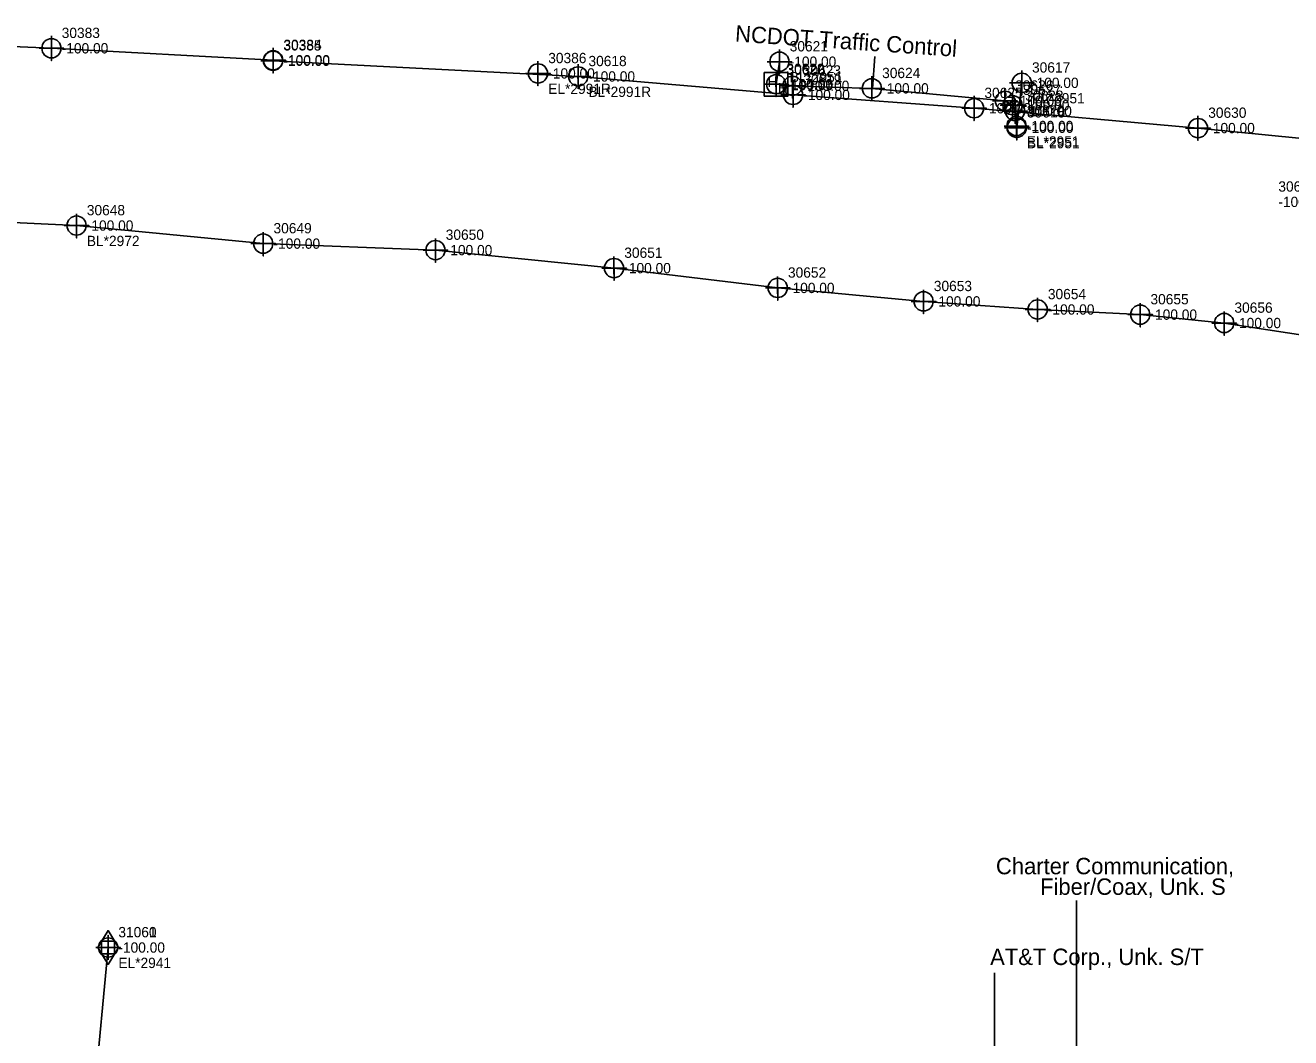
# Model space of a CAD drawing. Extents: x 2083698 to 2094313, y 743246 to 752873.
# Drawn here: x 2089753.4 to 2090061.4, y 744411.5 to 744658 of the extents above; entities that cross this region are included whole.
import ezdxf

# ---------------------------------------------------------------- set-up
doc = ezdxf.new("R2010")
doc.units = 0
for name, color, linetype in [('COGO Default Chain', 7, 'Continuous'), ('COGO Default Curve', 7, 'Continuous'), ('COGO Default Point Number', 7, 'Continuous'), ('COGO Default Spiral', 7, 'Continuous'), ('Exist Other Culture Fence Line', 7, 'Continuous'), ('Exist Property Iron Pin Leader', 7, 'Continuous'), ('Exist Property Iron Pin Text', 7, 'Continuous'), ('Exist Property Line', 7, 'Continuous'), ('Exist Property Monument Cogo Elevation', 7, 'Continuous'), ('Exist Property Monument Cogo Number', 7, 'Continuous'), ('Exist Property Monument Leader', 7, 'Continuous'), ('Exist Property Monument Text', 7, 'Continuous'), ('Exist Right of Way Easement Line', 7, 'Continuous'), ('Exist Right of Way Line', 7, 'Continuous'), ('Exist Right of Way Line Leader', 7, 'Continuous'), ('Exist Right of Way Line Text', 7, 'Continuous'), ('Exist Right of Way Width CELL', 7, 'Continuous'), ('Exist Utilities Gas Meter CELL', 7, 'Continuous'), ('Exist Utilities Gas Meter Cogo Elevation', 7, 'Continuous'), ('Exist Utilities Gas Meter Cogo Number', 7, 'Continuous'), ('Exist Utilities Gas UG Line SUE LOS B', 7, 'Continuous'), ('Exist Utilities Power UG Cable SUE LOS B', 7, 'Continuous'), ('Exist Utilities Power UG Cable SUE LOS B Leader', 7, 'Continuous'), ('Exist Utilities Power UG Cable SUE LOS B Text', 7, 'Continuous'), ('Exist Utilities Telephone UG Conduit SUE LOS B', 7, 'Continuous'), ('Exist Utilities Telephone UG Conduit SUE LOS B Leader', 7, 'Continuous'), ('Exist Utilities Telephone UG Conduit SUE LOS B Text', 7, 'Continuous'), ('Exist Utilities TV UG Cable SUE LOS B Leader', 7, 'Continuous'), ('Exist Utilities TV UG Cable SUE LOS B Text', 7, 'Continuous'), ('Exist Utilities Water UG Line SUE LOS B', 7, 'Continuous'), ('Old_Level_20', 7, 'Continuous'), ('Scratch_Level_2', 7, 'Continuous'), ('Scratch_Level_3', 7, 'Continuous'), ('Scratch_Level_5', 7, 'Continuous')]:
    doc.layers.add(name, color=color, linetype=linetype)

msp = doc.modelspace()

# ---------------------------------------------------------------- linework, layer by layer
at = {"layer": 'COGO Default Curve'}
msp.add_lwpolyline([(2089770.58, 744433.44), (2089776.58, 744433.44), (2089773.58, 744433.44), (2089773.58, 744436.44), (2089773.58, 744430.44)], dxfattribs=at)
msp.add_circle((2089773.58, 744433.44), 2.34, dxfattribs=at)
at = {"layer": 'COGO Default Point Number'}
for points in [[(2089759.79, 744655.4), (2089759.79, 744649.4), (2089759.79, 744652.4), (2089762.79, 744652.4), (2089756.79, 744652.4)], [(2089813.73, 744652.36), (2089813.73, 744646.36), (2089813.73, 744649.36), (2089816.73, 744649.36), (2089810.73, 744649.36)], [(2089813.76, 744652.5), (2089813.76, 744646.5), (2089813.76, 744649.5), (2089816.76, 744649.5), (2089810.76, 744649.5)], [(2089878.21, 744649.28), (2089878.21, 744643.28), (2089878.21, 744646.28), (2089881.21, 744646.28), (2089875.21, 744646.28)], [(2089888, 744648.55), (2089888, 744642.55), (2089888, 744645.55), (2089891, 744645.55), (2089885, 744645.55)], [(2089940.29, 744644.05), (2089940.29, 744638.05), (2089940.29, 744641.05), (2089943.29, 744641.05), (2089937.29, 744641.05)], [(2089984.37, 744640.8), (2089984.37, 744634.8), (2089984.37, 744637.8), (2089987.37, 744637.8), (2089981.37, 744637.8)], [(2090038.85, 744635.97), (2090038.85, 744629.97), (2090038.85, 744632.97), (2090041.85, 744632.97), (2090035.85, 744632.97)]]:
    msp.add_lwpolyline(points, dxfattribs=at)
for centre in [(2089759.79, 744652.4), (2089813.73, 744649.36), (2089813.76, 744649.5), (2089878.21, 744646.28), (2089888, 744645.55), (2089940.29, 744641.05), (2089984.37, 744637.8), (2090038.85, 744632.97)]:
    msp.add_circle(centre, 2.34, dxfattribs=at)
at = {"layer": 'COGO Default Spiral'}
msp.add_line((2089936.22, 744643.45), (2089936.22, 744643.45), dxfattribs=at)
msp.add_lwpolyline([(2089933.27, 744640.72), (2089939.02, 744640.72), (2089939.02, 744646.47), (2089933.27, 744646.47), (2089933.27, 744640.72)], dxfattribs=at)
at = {"layer": 'Exist Property Iron Pin Text'}
for points in [[(2089936.98, 744652.14), (2089936.98, 744646.14), (2089936.98, 744649.14), (2089939.98, 744649.14), (2089933.98, 744649.14)], [(2089936.17, 744646.65), (2089936.17, 744640.65), (2089936.17, 744643.65), (2089939.17, 744643.65), (2089933.17, 744643.65)], [(2089940.16, 744646.26), (2089940.16, 744640.26), (2089940.16, 744643.26), (2089943.16, 744643.26), (2089937.16, 744643.26)], [(2089995.96, 744646.99), (2089995.96, 744640.99), (2089995.96, 744643.99), (2089998.96, 744643.99), (2089992.96, 744643.99)], [(2089959.48, 744645.64), (2089959.48, 744639.64), (2089959.48, 744642.64), (2089962.48, 744642.64), (2089956.48, 744642.64)], [(2089991.87, 744642.6), (2089991.87, 744636.6), (2089991.87, 744639.6), (2089994.87, 744639.6), (2089988.87, 744639.6)], [(2089993.72, 744641.54), (2089993.72, 744635.54), (2089993.72, 744638.54), (2089996.72, 744638.54), (2089990.72, 744638.54)], [(2089994.32, 744640.1), (2089994.32, 744634.1), (2089994.32, 744637.1), (2089997.32, 744637.1), (2089991.32, 744637.1)], [(2089994.68, 744636.47), (2089994.68, 744630.47), (2089994.68, 744633.47), (2089997.68, 744633.47), (2089991.68, 744633.47)], [(2089994.74, 744636.05), (2089994.74, 744630.05), (2089994.74, 744633.05), (2089997.74, 744633.05), (2089991.74, 744633.05)]]:
    msp.add_lwpolyline(points, dxfattribs=at)
for centre in [(2089936.98, 744649.14), (2089936.17, 744643.65), (2089995.96, 744643.99), (2089940.16, 744643.26), (2089959.48, 744642.64), (2089991.87, 744639.6), (2089993.72, 744638.54), (2089994.32, 744637.1), (2089994.68, 744633.47), (2089994.74, 744633.05)]:
    msp.add_circle(centre, 2.34, dxfattribs=at)
at = {"layer": 'Exist Right of Way Line Text'}
for points in [[(2089765.87, 744612.05), (2089765.9, 744606.24), (2089765.88, 744609.24), (2089768.9, 744609.24), (2089762.9, 744609.24)], [(2089811.31, 744607.65), (2089811.34, 744601.84), (2089811.32, 744604.84), (2089814.34, 744604.84), (2089808.34, 744604.84)], [(2089853.23, 744606.08), (2089853.26, 744600.26), (2089853.25, 744603.26), (2089856.26, 744603.26), (2089850.26, 744603.26)], [(2089896.69, 744601.69), (2089896.72, 744595.87), (2089896.71, 744598.87), (2089899.72, 744598.87), (2089893.72, 744598.87)], [(2089936.53, 744596.87), (2089936.56, 744591.05), (2089936.54, 744594.05), (2089939.56, 744594.05), (2089933.56, 744594.05)], [(2089972.02, 744593.58), (2089972.06, 744587.77), (2089972.04, 744590.77), (2089975.06, 744590.77), (2089969.06, 744590.77)], [(2089999.79, 744591.61), (2089999.82, 744585.8), (2089999.8, 744588.8), (2090002.82, 744588.8), (2089996.82, 744588.8)], [(2090024.75, 744590.37), (2090024.79, 744584.55), (2090024.77, 744587.55), (2090027.79, 744587.55), (2090021.79, 744587.55)], [(2090045.2, 744588.31), (2090045.23, 744582.5), (2090045.21, 744585.5), (2090048.23, 744585.5), (2090042.23, 744585.5)]]:
    msp.add_lwpolyline(points, dxfattribs=at)
for centre in [(2089765.9, 744609.24), (2089811.34, 744604.84), (2089853.26, 744603.26), (2089896.72, 744598.87), (2089936.56, 744594.05), (2089972.06, 744590.77), (2089999.82, 744588.8), (2090024.79, 744587.55), (2090045.23, 744585.5)]:
    msp.add_circle(centre, 2.34, dxfattribs=at)
at = {"layer": 'Exist Utilities Gas Meter CELL'}
msp.add_line((2089773.58, 744433.43), (2089773.58, 744433.43), dxfattribs=at)
for points in [[(2089771.04, 744433.43), (2089773.58, 744437.55), (2089776.11, 744433.43), (2089773.58, 744429.32), (2089771.04, 744433.43)], [(2089772, 744434.97), (2089775.15, 744434.97), (2089775.15, 744431.86), (2089772, 744431.86), (2089772, 744434.97)]]:
    msp.add_lwpolyline(points, dxfattribs=at)
at = {"layer": 'Exist Utilities Gas UG Line SUE LOS B'}
msp.add_lwpolyline([(2089773.58, 744433.44), (2089770.29, 744398.03), (2089770.13, 744385.56)], dxfattribs=at)
at = {"layer": 'Exist Utilities Power UG Cable SUE LOS B'}
msp.add_line((2089994.74, 744633.05), (2089995.96, 744643.99), dxfattribs=at)
msp.add_lwpolyline([(2089936.98, 744649.14), (2089936.17, 744643.65), (2089940.16, 744643.26), (2089959.48, 744642.64), (2089991.87, 744639.6), (2089993.72, 744638.54), (2089994.32, 744637.1), (2089994.68, 744633.47)], dxfattribs=at)
at = {"layer": 'Exist Utilities Power UG Cable SUE LOS B Leader'}
msp.add_line((2089959.65, 744642.62), (2089960.18, 744650.36), dxfattribs=at)
at = {"layer": 'Exist Utilities Telephone UG Conduit SUE LOS B'}
for points in [[(2089692.08, 744612.74), (2089765.9, 744609.24)], [(2089765.9, 744609.24), (2089811.34, 744604.84), (2089853.26, 744603.26), (2089896.72, 744598.87), (2089936.56, 744594.05), (2089972.06, 744590.77), (2089999.82, 744588.8), (2090024.79, 744587.55), (2090045.23, 744585.5), (2090102.13, 744576.81), (2090142.55, 744572.19), (2090182.46, 744566.17), (2090246.9, 744558.49), (2090290.17, 744552.93), (2090290.13, 744552.92), (2090326.6, 744546.35), (2090355.01, 744537.98), (2090386.28, 744530.9), (2090411.39, 744527.69), (2090440.1, 744525.73), (2090475.39, 744519.24), (2090503.67, 744513), (2090507.42, 744510.61), (2090511.18, 744507.33)]]:
    msp.add_lwpolyline(points, dxfattribs=at)
at = {"layer": 'Exist Utilities Telephone UG Conduit SUE LOS B Leader'}
msp.add_line((2089989.3, 744386.66), (2089989.3, 744427.25), dxfattribs=at)
at = {"layer": 'Exist Utilities TV UG Cable SUE LOS B Leader'}
msp.add_line((2090009.26, 744390.92), (2090009.26, 744444.87), dxfattribs=at)
at = {"layer": 'Exist Utilities Water UG Line SUE LOS B'}
for points in [[(2089713.78, 744654.4), (2089759.79, 744652.4), (2089813.76, 744649.5), (2089813.73, 744649.36), (2089888, 744645.55)], [(2089888, 744645.55), (2089940.29, 744641.05), (2089984.37, 744637.8), (2090038.85, 744632.97), (2090088.77, 744627.99), (2090100.38, 744626.26), (2090124.41, 744620.89), (2090164.85, 744611.65), (2090206.05, 744605.57), (2090290.62, 744579.58), (2090366.03, 744562.99), (2090413.47, 744552.79), (2090451.59, 744545.38), (2090451.65, 744545.48), (2090528.38, 744534.81)]]:
    msp.add_lwpolyline(points, dxfattribs=at)

# ---------------------------------------------------------------- texts
at = {"layer": 'COGO Default Chain'}
msp.add_text('-100.00', height=2.5, dxfattribs=at).set_placement((2089776.08, 744432.19))
at = {"layer": 'COGO Default Spiral'}
for p in [(2089934.07, 744642.97), (2089936.63, 744641.45)]:
    msp.add_text('H', height=2.5, dxfattribs=at).set_placement(p)
at = {"layer": 'Exist Other Culture Fence Line'}
msp.add_text('-100.00', height=2.5, dxfattribs=at).set_placement((2089938.72, 744642.2))
at = {"layer": 'Exist Property Iron Pin Leader'}
for s, p in [('30621', (2089939.48, 744651.64)), ('30617', (2089998.46, 744646.49)), ('30622', (2089938.67, 744646.15)), ('30623', (2089942.66, 744645.76)), ('30624', (2089961.98, 744645.14)), ('30626', (2089994.37, 744642.1)), ('30627', (2089996.22, 744641.04)), ('30628', (2089996.82, 744639.6)), ('30629', (2089997.18, 744635.97)), ('30616', (2089997.24, 744635.55))]:
    msp.add_text(s, height=2.5, dxfattribs=at).set_placement(p)
at = {"layer": 'Exist Property Line'}
for p in [(2089762.29, 744651.15), (2089816.23, 744648.11), (2089816.26, 744648.25), (2089880.71, 744645.03), (2089890.5, 744644.3), (2089942.79, 744639.8), (2089986.87, 744636.55), (2090041.35, 744631.72)]:
    msp.add_text('-100.00', height=2.5, dxfattribs=at).set_placement(p)
at = {"layer": 'Exist Property Monument Cogo Elevation'}
for p in [(2089997.22, 744631.8), (2090058.42, 744613.75)]:
    msp.add_text('-100.00', height=2.5, dxfattribs=at).set_placement(p)
at = {"layer": 'Exist Property Monument Cogo Number'}
for s, p in [('30615', (2089997.22, 744635.55)), ('30647', (2090058.42, 744617.5))]:
    msp.add_text(s, height=2.5, dxfattribs=at).set_placement(p)
at = {"layer": 'Exist Property Monument Leader'}
for s, p in [('BL*2951', (2089939.48, 744644.14)), ('EL*2951', (2089998.46, 744638.99)), ('EL*2951', (2089997.18, 744628.47)), ('BL*2951', (2089997.24, 744628.05))]:
    msp.add_text(s, height=2.5, dxfattribs=at).set_placement(p)
at = {"layer": 'Exist Property Monument Text'}
for p in [(2089939.48, 744647.89), (2089938.67, 744642.4), (2089942.66, 744642.01), (2089961.98, 744641.39), (2089998.46, 744642.74), (2089994.37, 744638.35), (2089996.22, 744637.29), (2089996.82, 744635.85), (2089997.18, 744632.22), (2089997.24, 744631.8)]:
    msp.add_text('-100.00', height=2.5, dxfattribs=at).set_placement(p)
at = {"layer": 'Exist Right of Way Easement Line'}
msp.add_text('EL*2941', height=2.5, dxfattribs=at).set_placement((2089776.08, 744428.44))
at = {"layer": 'Exist Right of Way Line'}
for s, p in [('30383', (2089762.29, 744654.9)), ('30385', (2089816.23, 744651.86)), ('30384', (2089816.26, 744652)), ('30386', (2089880.71, 744648.78)), ('30618', (2089890.5, 744648.05)), ('30619', (2089942.79, 744643.55)), ('30625', (2089986.87, 744640.3)), ('30630', (2090041.35, 744635.47))]:
    msp.add_text(s, height=2.5, dxfattribs=at).set_placement(p)
at = {"layer": 'Exist Right of Way Line Leader'}
for s, p in [('30648', (2089768.4, 744611.74)), ('30649', (2089813.84, 744607.34)), ('30650', (2089855.76, 744605.76)), ('30651', (2089899.22, 744601.37)), ('30652', (2089939.06, 744596.55)), ('30653', (2089974.56, 744593.27)), ('30654', (2090002.32, 744591.3)), ('30655', (2090027.29, 744590.05)), ('30656', (2090047.73, 744588))]:
    msp.add_text(s, height=2.5, dxfattribs=at).set_placement(p)
at = {"layer": 'Exist Right of Way Width CELL'}
for s, p in [('EL*2991R', (2089880.71, 744641.28)), ('BL*2991R', (2089890.5, 744640.55))]:
    msp.add_text(s, height=2.5, dxfattribs=at).set_placement(p)
at = {"layer": 'Exist Utilities Gas Meter Cogo Elevation'}
msp.add_text('-100.00', height=2.5, dxfattribs=at).set_placement((2089776.08, 744432.18))
at = {"layer": 'Exist Utilities Gas Meter Cogo Number'}
msp.add_text('31061', height=2.5, dxfattribs=at).set_placement((2089776.08, 744435.93))
at = {"layer": 'Exist Utilities Power UG Cable SUE LOS B Text'}
msp.add_text('NCDOT Traffic Control', height=4, rotation=356.0628, dxfattribs=at).set_placement((2089926.1, 744654.04))
at = {"layer": 'Exist Utilities Telephone UG Conduit SUE LOS B Text'}
msp.add_text('AT&T Corp., Unk. S/T', height=4, dxfattribs=at).set_placement((2089988.27, 744429.17))
at = {"layer": 'Exist Utilities TV UG Cable SUE LOS B Text'}
for s, p in [('Charter Communication, ', (2089989.68, 744451.27)), ('Fiber/Coax, Unk. S', (2090000.42, 744446.26))]:
    msp.add_text(s, height=4, dxfattribs=at).set_placement(p)
at = {"layer": 'Old_Level_20'}
msp.add_text('31060', height=2.5, dxfattribs=at).set_placement((2089776.08, 744435.94))
at = {"layer": 'Scratch_Level_2'}
for p in [(2089768.4, 744607.99), (2089813.84, 744603.59), (2089855.76, 744602.01), (2089899.22, 744597.62), (2089939.06, 744592.8), (2089974.56, 744589.52), (2090002.32, 744587.55), (2090027.29, 744586.3), (2090047.73, 744584.25)]:
    msp.add_text('-100.00', height=2.5, dxfattribs=at).set_placement(p)
at = {"layer": 'Scratch_Level_3'}
msp.add_text('BL*2972', height=2.5, dxfattribs=at).set_placement((2089768.4, 744604.24))
at = {"layer": 'Scratch_Level_5'}
msp.add_text('30620', height=2.5, dxfattribs=at).set_placement((2089938.72, 744645.95))

doc.saveas('drawing.dxf')
